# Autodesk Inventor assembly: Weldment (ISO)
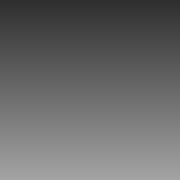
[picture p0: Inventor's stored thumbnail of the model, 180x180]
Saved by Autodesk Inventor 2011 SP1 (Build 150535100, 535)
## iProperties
Length Units: 11269
Angle Units: 11283
Time Units: 11279
Mass Units: 11290
Length Display Precision: 3
Angle Display Precision: 2
Part Number: Weldment (ISO)
Document SubType Name: Weldment
Created: 2002-06
Designer: smithga
Created: 2002-08
Weld Material: Welded Aluminum-6061
Control State: 0
Master: False
Shininess: 64.0
Angle Units: 11279
Time Units: 11290
Mass Units: 11283
Compacted: True
Density: 0.0
Volumn: 0.0
Area: 0.0
PropertySet Name: Model Information
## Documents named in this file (1)
- M:\Programs\AUT_Inventor2011EN\Templates\Weldment.iam
